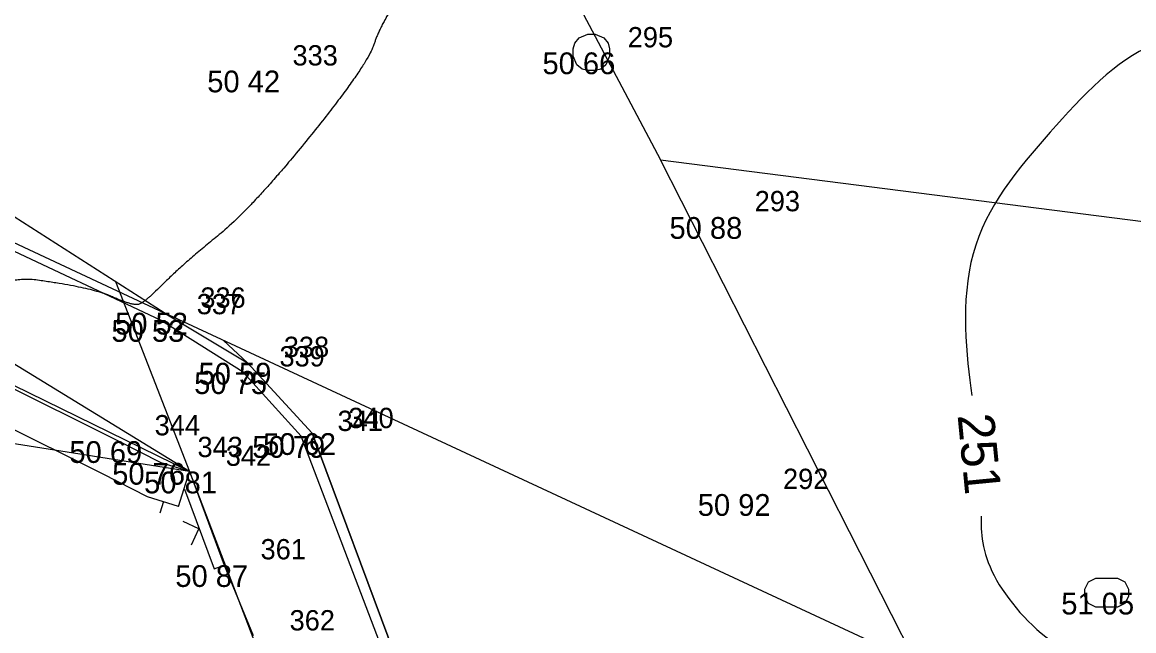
# Model space of a CAD drawing. Extents: x -704057 to -703795, y -1008732 to -1008584.
# Drawn here: x -703998.45 to -703983.13, y -1008656.35 to -1008647.96 of the extents above; entities that cross this region are included whole.
import ezdxf

# ---------------------------------------------------------------- set-up
doc = ezdxf.new("R2010")
doc.units = 0
for name, color, linetype in [('Z_body', 7, 'Continuous'), ('Z_body_cisla', 7, 'Continuous'), ('Z_body_vysky', 7, 'Continuous'), ('Z_katastr_hranice', 7, 'Continuous'), ('Z_katastr_hranice_KU', 7, 'Continuous'), ('Z_katastr_vnitrni_kresba', 7, 'Continuous'), ('Z_komunikace_zpevn_pl', 7, 'Continuous'), ('Z_obruby', 7, 'Continuous'), ('Z_oploceni', 7, 'Continuous'), ('Z_site_znaky_kanalizace', 7, 'Continuous'), ('Z_site_znaky_plyn', 7, 'Continuous'), ('Z_vrstevnice_popis', 7, 'Continuous'), ('Z_vrstevnice_vedlejsi', 7, 'Continuous'), ('Z_vstupy', 7, 'Continuous')]:
    doc.layers.add(name, color=color, linetype=linetype)

# ---------------------------------------------------------------- blocks, each defined once
blk = doc.blocks.new('POINT_DISPLAY')
blk.add_line((0, 0), (0, 0))
blk = doc.blocks.new('Z210')
blk.add_line((0, 0), (0, 0.17))
blk = doc.blocks.new('Z212')
for p, q in [((-0.17, 0.17), (0, 0)), ((0, 0), (0.17, 0.17))]:
    blk.add_line(p, q)
blk = doc.blocks.new('Z620')
for p, q in [((-0.23, 0.13), (-0.17, 0.2)), ((-0.17, 0.2), (-0.05, 0.25)), ((-0.05, 0.25), (0.05, 0.25)), ((0.05, 0.25), (0.17, 0.2)), ((0.17, 0.2), (0.23, 0.13)), ((-0.25, 0.05), (-0.23, 0.13)), ((-0.25, -0.05), (-0.25, 0.05)), ((0.23, 0.13), (0.25, 0.05)), ((0.25, 0.05), (0.25, -0.05)), ((-0.2, -0.17), (-0.25, -0.05)), ((0.25, -0.05), (0.2, -0.17)), ((-0.13, -0.23), (-0.2, -0.17)), ((-0.05, -0.25), (-0.13, -0.23)), ((0.05, -0.25), (-0.05, -0.25)), ((0.13, -0.23), (0.05, -0.25)), ((0.2, -0.17), (0.13, -0.23))]:
    blk.add_line(p, q)
blk = doc.blocks.new('Z14')
for p, q in [((-0.25, 0.15), (-0.15, 0.2)), ((-0.15, 0.2), (0.15, 0.2)), ((0.15, 0.2), (0.25, 0.15)), ((-0.3, 0.05), (-0.25, 0.15)), ((-0.3, -0.05), (-0.3, 0.05)), ((0.25, 0.15), (0.3, 0.05)), ((0.3, 0.05), (0.3, -0.05)), ((-0.25, -0.15), (-0.3, -0.05)), ((-0.15, -0.2), (-0.25, -0.15)), ((0.25, -0.15), (0.15, -0.2)), ((0.3, -0.05), (0.25, -0.15)), ((0.15, -0.2), (-0.15, -0.2))]:
    blk.add_line(p, q)

msp = doc.modelspace()

# ---------------------------------------------------------------- linework, layer by layer
at = {"layer": 'Z_katastr_hranice'}
for p, q in [((-703996.49, -1008651.97), (-704013.74, -1008640.92)), ((-703996.14, -1008654.16), (-704025.87, -1008649.43)), ((-703996.14, -1008654.16), (-704004.85, -1008649.89)), ((-703986.13, -1008656.79), (-703989.65, -1008649.86)), ((-703997.16, -1008651.54), (-703996.14, -1008654.16)), ((-703986.13, -1008656.79), (-703996.49, -1008651.97)), ((-703995.34, -1008652.66), (-703995.67, -1008652.35)), ((-703994.45, -1008653.63), (-703995.34, -1008652.66)), ((-703992.64, -1008658.49), (-703994.45, -1008653.63)), ((-703996.14, -1008654.16), (-703988.54, -1008674.06))]:
    msp.add_line(p, q, dxfattribs=at)
at = {"layer": 'Z_katastr_hranice_KU'}
for p, q in [((-703992.18, -1008645.08), (-703989.65, -1008649.86)), ((-703989.65, -1008649.86), (-703970.06, -1008652.37))]:
    msp.add_line(p, q, dxfattribs=at)
at = {"layer": 'Z_katastr_vnitrni_kresba'}
msp.add_line((-703996.14, -1008654.16), (-704013.51, -1008643.51), dxfattribs=at)
at = {"layer": 'Z_komunikace_zpevn_pl'}
for p, q in [((-703999.67, -1008650.48), (-703996.49, -1008651.97)), ((-703996.49, -1008651.97), (-703995.34, -1008652.66)), ((-703995.34, -1008652.66), (-703994.45, -1008653.63)), ((-703994.45, -1008653.63), (-703992.64, -1008658.49))]:
    msp.add_line(p, q, dxfattribs=at)
at = {"layer": 'Z_obruby'}
for p, q in [((-703996.54, -1008652.07), (-703999.75, -1008650.56)), ((-703995.4, -1008652.79), (-703996.54, -1008652.07)), ((-703994.6, -1008653.67), (-703995.4, -1008652.79)), ((-703992.74, -1008658.56), (-703994.6, -1008653.67))]:
    msp.add_line(p, q, dxfattribs=at)
at = {"layer": 'Z_oploceni'}
for p, q in [((-703997.12, -1008653.74), (-704004.85, -1008649.89)), ((-703997.34, -1008654.19), (-704005.09, -1008650.33)), ((-703996.53, -1008654.04), (-703997.12, -1008653.74)), ((-703996.14, -1008654.16), (-703996.53, -1008654.04)), ((-703996.72, -1008654.51), (-703997.34, -1008654.19)), ((-703996.29, -1008654.64), (-703996.14, -1008654.16)), ((-703996.14, -1008654.16), (-703995.66, -1008655.45)), ((-703996.29, -1008654.64), (-703996.72, -1008654.51)), ((-703996.21, -1008654.4), (-703995.8, -1008655.5)), ((-703995.8, -1008655.5), (-703995.66, -1008655.45))]:
    msp.add_line(p, q, dxfattribs=at)
at = {"layer": 'Z_vrstevnice_popis'}
for points in [[(-703989.503, -1008643.449), (-703989.267, -1008643.557), (-703988.594, -1008643.878), (-703987.719, -1008644.81), (-703986.755, -1008645.399), (-703986.308, -1008645.619), (-703984.807, -1008646.186), (-703985.704, -1008645.225), (-703986.427, -1008644.081), (-703986.268, -1008643.227), (-703985.558, -1008644.406), (-703985.308, -1008644.79), (-703982.136, -1008647.335), (-703982.104, -1008647.377), (-703980.996, -1008647.981), (-703981.138, -1008648.096), (-703981.236, -1008648.238), (-703982.91, -1008647.991), (-703984.29, -1008649.466), (-703985.601, -1008651.032), (-703985.434, -1008652.571), (-703985.359, -1008653.111)], [(-703985.231, -1008654.773), (-703985.233, -1008654.99), (-703985.209, -1008655.538), (-703984.22, -1008656.692), (-703983.2, -1008656.858), (-703982.505, -1008657.462), (-703981.889, -1008657.948), (-703981.945, -1008658.047), (-703982.027, -1008658.206), (-703982.128, -1008658.577), (-703982.119, -1008658.578), (-703981.97, -1008658.325), (-703981.459, -1008658.081), (-703981.513, -1008658.577), (-703981.415, -1008659.217), (-703981.332, -1008659.732), (-703980.559, -1008660.215), (-703980.405, -1008660.435), (-703979.463, -1008659.63), (-703979.059, -1008659.888), (-703977.693, -1008660.229), (-703973.778, -1008660.657)]]:
    msp.add_open_spline(points, degree=3, dxfattribs=at)
at = {"layer": 'Z_vrstevnice_vedlejsi'}
for points in [[(-704009.362, -1008633.586), (-704007.915, -1008634.739), (-704007.143, -1008635.358), (-704002.876, -1008638.286), (-704002.679, -1008638.43), (-704002.255, -1008638.718), (-704001.165, -1008638.717), (-703995.889, -1008642.289), (-703994.89, -1008642.862), (-703994.417, -1008642.752), (-703993.832, -1008642.719), (-703993.258, -1008640.696), (-703993.341, -1008639.701), (-703993.272, -1008639.432), (-703993.04, -1008638.835), (-703992.99, -1008638.745), (-703990.403, -1008638.423), (-703989.481, -1008638.539), (-703989.058, -1008638.588), (-703989.018, -1008638.516), (-703988.578, -1008638.54), (-703988.475, -1008638.554), (-703988.362, -1008638.685), (-703988.319, -1008638.754), (-703988.294, -1008638.815), (-703986.637, -1008641.391), (-703986.518, -1008641.581), (-703985.267, -1008643.657), (-703984.422, -1008644.955), (-703982.223, -1008646.72), (-703982.083, -1008646.9), (-703980.47, -1008647.779), (-703979.335, -1008647.914), (-703971.793, -1008648.878), (-703969.312, -1008649.063), (-703968.076, -1008649.117), (-703960.948, -1008649.919), (-703959.282, -1008650.186), (-703958.493, -1008650.28), (-703957.367, -1008650.455), (-703955.116, -1008650.684), (-703950.816, -1008651.182), (-703948.3, -1008651.463), (-703946.953, -1008651.576), (-703945.397, -1008651.505), (-703943.023, -1008651.703), (-703939.161, -1008651.987), (-703938.27, -1008652.079), (-703937.191, -1008652.194), (-703934.147, -1008651.524), (-703931.028, -1008650.815), (-703930.717, -1008650.764), (-703928.94, -1008650.83), (-703928.501, -1008650.751), (-703928.424, -1008650.713), (-703928.413, -1008650.708), (-703928.266, -1008650.724), (-703926.027, -1008648.737), (-703920.5, -1008648.624), (-703915.824, -1008649.925), (-703908.88, -1008649.843), (-703904.651, -1008650.155), (-703897.103, -1008651.333), (-703893.743, -1008651.997), (-703889.99, -1008652.252), (-703881.693, -1008653.228), (-703874.656, -1008652.961), (-703868.448, -1008652.365), (-703859.857, -1008652.906), (-703856.36, -1008653.001), (-703843.765, -1008653.766), (-703842.17, -1008653.801), (-703841.143, -1008653.824), (-703831.904, -1008654.28)], [(-704010.305, -1008634.308), (-704009.364, -1008635.058), (-704007.05, -1008636.913), (-704005.077, -1008638.267), (-704003.784, -1008639.207), (-704001.007, -1008641.096), (-704000.569, -1008641.096), (-703998.452, -1008642.529), (-703996.572, -1008643.608), (-703994.455, -1008644.81), (-703993.69, -1008644.725), (-703993.267, -1008644.95), (-703992.917, -1008644.879), (-703992.134, -1008645.881), (-703992.595, -1008646.639), (-703993.503, -1008647.958), (-703993.68, -1008648.547), (-703995.276, -1008650.526), (-703996.236, -1008651.302), (-703996.767, -1008651.84), (-703996.931, -1008651.871), (-703997.503, -1008651.617), (-703999.042, -1008651.416), (-703999.451, -1008652.579)]]:
    msp.add_open_spline(points, degree=2, dxfattribs=at)
at = {"layer": 'Z_vstupy'}
msp.add_line((-703995.66, -1008655.45), (-703995.26, -1008656.42), dxfattribs=at)

# ---------------------------------------------------------------- block references
at = {"layer": 'Z_body'}
for p in [(-703990.6, -1008648.38), (-703995.22, -1008648.63), (-703988.85, -1008650.65), (-703996.54, -1008652.07), (-703996.49, -1008651.97), (-703995.34, -1008652.66), (-703995.4, -1008652.79), (-703994.45, -1008653.63), (-703997.12, -1008653.74), (-703994.6, -1008653.67), (-703996.53, -1008654.04), (-703996.14, -1008654.16), (-703988.46, -1008654.47), (-703995.66, -1008655.45), (-703983.5, -1008655.83)]:
    msp.add_blockref('POINT_DISPLAY', p, dxfattribs=at)
at = {"layer": 'Z_oploceni'}
for name, p, rotation in [('Z210', (-703996.5, -1008654.57), 162.9), ('Z212', (-703996.01, -1008654.95), 110.4)]:
    msp.add_blockref(name, p, dxfattribs=dict(at, rotation=rotation))
at = {"layer": 'Z_site_znaky_kanalizace'}
msp.add_blockref('Z620', (-703990.6, -1008648.38), dxfattribs=at)
at = {"layer": 'Z_site_znaky_plyn'}
msp.add_blockref('Z14', (-703983.5, -1008655.83), dxfattribs=at)

# ---------------------------------------------------------------- texts
at = {"layer": 'Z_body_cisla'}
for s, p in [('295', (-703990.1, -1008648.31)), ('333', (-703994.72, -1008648.56)), ('293', (-703988.35, -1008650.57)), ('336', (-703995.99, -1008651.9)), ('337', (-703996.04, -1008651.99)), ('338', (-703994.84, -1008652.58)), ('339', (-703994.9, -1008652.71)), ('341', (-703994.1, -1008653.6)), ('340', (-703993.95, -1008653.56)), ('344', (-703996.62, -1008653.66)), ('343', (-703996.03, -1008653.96)), ('342', (-703995.64, -1008654.08)), ('292', (-703987.96, -1008654.4)), ('361', (-703995.16, -1008655.37)), ('362', (-703994.76, -1008656.35))]:
    msp.add_text(s, height=0.28, dxfattribs=at).set_placement(p)
at = {"layer": 'Z_body_vysky'}
for s, p in [('50 66', (-703991.275, -1008648.68)), ('50 42', (-703995.895, -1008648.93)), ('50 88', (-703989.525, -1008650.95)), ('50 53', (-703997.215, -1008652.37)), ('50 52', (-703997.165, -1008652.27)), ('50 59', (-703996.015, -1008652.96)), ('50 75', (-703996.075, -1008653.09)), ('50 62', (-703995.125, -1008653.93)), ('50 69', (-703997.795, -1008654.04)), ('50 79', (-703995.275, -1008653.97)), ('50 76', (-703997.205, -1008654.34)), ('50 81', (-703996.765, -1008654.46)), ('50 92', (-703989.135, -1008654.77)), ('50 87', (-703996.335, -1008655.75)), ('51 05', (-703984.125, -1008656.13))]:
    msp.add_text(s, height=0.3, dxfattribs=at).set_placement(p)
at = {"layer": 'Z_vrstevnice_popis'}
msp.add_text('251', height=0.5, rotation=275.5772, dxfattribs=at).set_placement((-703985.555, -1008653.382))

doc.saveas('drawing.dxf')
